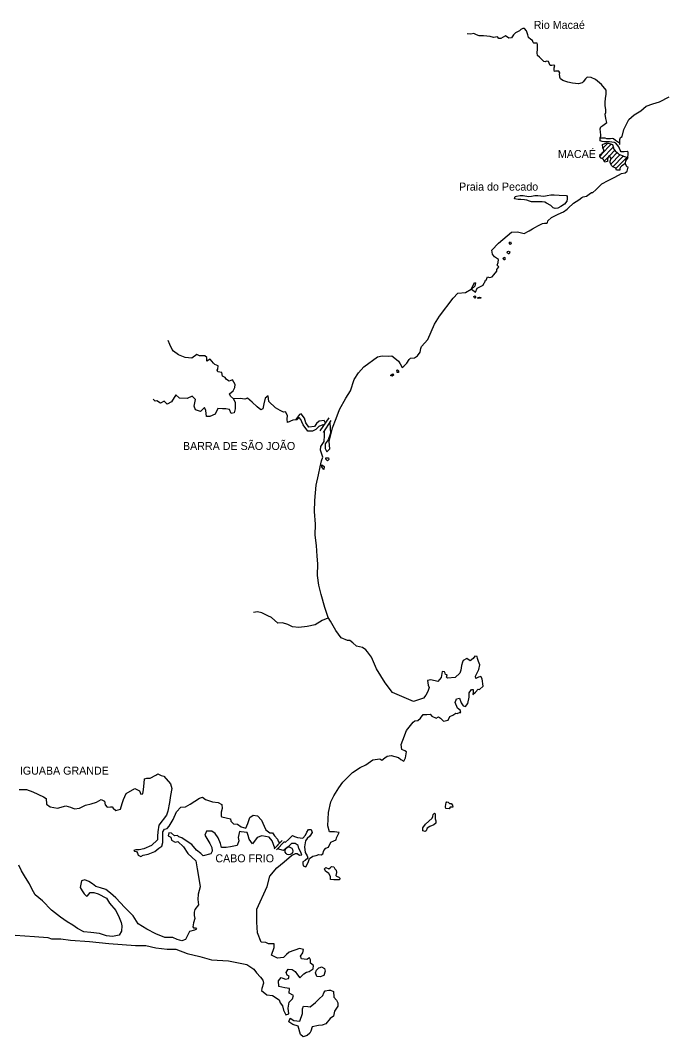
# Model space of a CAD drawing. Extents: x 662444 to 1640468, y 7452018 to 9606170.
# Drawn here: x 785069 to 836306, y 7452018 to 7532313 of the extents above; entities that cross this region are included whole.
import ezdxf

# ---------------------------------------------------------------- set-up
doc = ezdxf.new("R2010")
doc.units = 0
for name, color, linetype in [('Level 1', 7, 'Continuous'), ('Level 2', 7, 'Continuous'), ('Level 3', 7, 'Continuous')]:
    doc.layers.add(name, color=color, linetype=linetype)

msp = doc.modelspace()

# ---------------------------------------------------------------- linework, layer by layer
at = {"layer": 'Level 1'}
for points in [[(824206, 7531329), (824051, 7531162), (823878, 7530927), (823683, 7530899), (823398, 7531094), (823043, 7530879), (822878, 7530883), (822767, 7531007), (822466, 7530958), (822200, 7531030), (821665, 7531096), (821334, 7531092), (821109, 7531174), (820905, 7531267), (820667, 7531228), (820378, 7531234)], [(833086, 7521488), (833112, 7521743), (833115, 7521898), (833013, 7521956), (832785, 7521916), (832559, 7521921), (832469, 7522045), (832371, 7522324), (832141, 7522617), (832018, 7522664), (831822, 7522680), (831637, 7522717), (831421, 7522721), (831225, 7522726), (831050, 7522729), (830897, 7522799), (830891, 7523021), (830935, 7523164), (830938, 7523275), (830911, 7523486), (830896, 7523753), (830951, 7523907), (831108, 7524003), (831412, 7524241), (831347, 7524552), (831292, 7524897), (831336, 7525029), (831331, 7525251), (831296, 7525573), (831282, 7525851), (831309, 7526150), (831367, 7526481), (831353, 7526803), (831002, 7527254), (830515, 7527630), (830168, 7527804), (829859, 7527810), (829732, 7527691), (829552, 7527462), (829478, 7527386), (829188, 7527292), (828704, 7527358), (828334, 7527421), (827945, 7527552), (827752, 7527689), (827713, 7527823), (827704, 7527889), (827687, 7528034), (827710, 7528155), (827620, 7528290), (827362, 7528296), (827279, 7528264), (827262, 7528409), (827265, 7528564), (827300, 7528751), (827197, 7528776), (827062, 7528734), (826938, 7528737), (826850, 7528938), (826801, 7529050), (826770, 7529073), (826646, 7529076), (826552, 7529022), (826440, 7529069), (826289, 7529227), (826096, 7529409), (825934, 7529545), (825907, 7529734), (825934, 7530044), (825947, 7530155), (825952, 7530409), (825903, 7530521), (825645, 7530505), (825605, 7530561), (825546, 7530717), (825424, 7530786), (825231, 7530957), (825174, 7531180), (825077, 7531492), (824906, 7531662), (824777, 7531670), (824633, 7531580), (824519, 7531476), (824355, 7531411), (824206, 7531329)], [(830891, 7523021), (831066, 7523017), (831252, 7523024), (831395, 7522977), (831715, 7522981), (831850, 7523012), (831942, 7522987), (832104, 7522851), (832430, 7522633), (832427, 7522500), (832438, 7522544), (832446, 7522910), (832490, 7523064), (832636, 7523139), (832762, 7523691), (833170, 7524469), (833571, 7524859), (834103, 7525170), (834524, 7525526), (835043, 7525715), (835583, 7525880), (836355, 7526263)], [(823880, 7515576), (824359, 7515606), (824886, 7515465), (825292, 7515679), (825532, 7515829), (825793, 7515978), (825971, 7516086), (826325, 7516255), (826490, 7516296), (826532, 7516295), (826655, 7516282), (826686, 7516292), (826728, 7516325), (826762, 7516468), (827056, 7516728), (827577, 7517005), (828004, 7517184), (828276, 7517389), (828360, 7517476), (828781, 7517855), (829209, 7518134), (829450, 7518307), (829554, 7518360), (829803, 7518421), (830033, 7518582), (830211, 7518712), (830314, 7518710), (830546, 7518926), (830757, 7519144), (831020, 7519404), (831531, 7519659), (832000, 7519893), (832333, 7520074), (832584, 7520213), (832863, 7520262), (833021, 7520392), (833100, 7520723), (832987, 7520748), (832880, 7521038), (832764, 7520919), (832659, 7520843), (832565, 7520779), (832502, 7520703), (832438, 7520615), (832436, 7520527), (832435, 7520482), (832332, 7520485), (832188, 7520488), (832139, 7520622), (831883, 7520727), (831803, 7520817), (831684, 7521042), (831687, 7521197), (831764, 7521406), (831664, 7521563), (831624, 7521608), (831551, 7521555), (831464, 7521346), (831460, 7521157), (831252, 7521095), (831134, 7521353), (830960, 7521434), (830870, 7521558), (830895, 7521735), (831008, 7521732), (831041, 7521832), (831062, 7521864), (831166, 7521906), (831171, 7522117), (831112, 7522251), (831076, 7522507), (831253, 7522570), (831450, 7522632), (831870, 7522490), (831975, 7522122), (832086, 7522009), (832268, 7521839), (832379, 7521736), (832625, 7521631), (832747, 7521584), (833086, 7521488), (833011, 7521357), (832948, 7521303), (832884, 7521216), (832880, 7521038)], [(831767, 7522526), (831008, 7521744)], [(831928, 7522300), (831042, 7521399)], [(831491, 7522620), (831122, 7522240)], [(830998, 7521733), (830881, 7521602)], [(831540, 7521522), (831213, 7521185)], [(832046, 7522043), (831624, 7521608)], [(832461, 7521701), (831734, 7520952)], [(832238, 7521861), (831742, 7521351)], [(832727, 7521596), (831883, 7520727)], [(833014, 7521512), (832139, 7520611)], [(832436, 7520527), (832394, 7520483)], [(827536, 7517471), (827339, 7517453), (827186, 7517490), (826984, 7517683), (826657, 7517856), (826525, 7517936), (826299, 7517963), (825825, 7517973), (825701, 7517976), (825464, 7517981), (825311, 7518028), (825106, 7518110), (824911, 7518126), (824623, 7518154), (824406, 7518158), (824109, 7518220), (824164, 7518396), (824288, 7518427), (824578, 7518465), (824794, 7518461), (824928, 7518458), (825246, 7518407), (825473, 7518413), (825722, 7518485), (825969, 7518469), (826443, 7518426), (826712, 7518476), (827002, 7518536), (827269, 7518530), (827640, 7518511), (828227, 7518477), (828287, 7518387), (828283, 7518221), (828259, 7518022), (828068, 7517782), (827786, 7517610), (827536, 7517471)], [(809286, 7498216), (809518, 7498467), (809468, 7499044), (809747, 7500125), (810019, 7500862), (810301, 7501566), (810803, 7502453), (811155, 7503045), (811461, 7503937), (811801, 7504473), (812212, 7504930), (813289, 7505717), (813651, 7505799), (814145, 7505789), (814423, 7505794), (814657, 7505612), (814950, 7505373), (815080, 7505182), (815249, 7504890), (815375, 7504998), (815607, 7505238), (815787, 7505511), (815913, 7505619), (816213, 7505657), (816452, 7505797), (816654, 7506092), (816732, 7506378), (816766, 7506533), (817272, 7507088), (817791, 7508297), (818196, 7508942), (819266, 7510372), (819655, 7510752), (820254, 7510806), (820692, 7511074), (820863, 7511370), (820971, 7511590), (821043, 7511577), (820976, 7511312), (820734, 7511074), (821028, 7510846), (821179, 7511164), (821647, 7511398), (821713, 7511585), (821775, 7511617), (821841, 7511782), (821882, 7511792), (821990, 7512045), (822144, 7511998), (822361, 7512037), (822488, 7512212), (822731, 7512484), (822724, 7512628), (822873, 7512847), (822741, 7512972), (822828, 7513180), (822864, 7513413), (822549, 7513630), (822389, 7513844), (822343, 7514155), (822870, 7514698), (823880, 7515576)], [(823552, 7513984), (823569, 7514052), (823640, 7514084), (823742, 7514015), (823708, 7513860), (823636, 7513862), (823575, 7513919), (823552, 7513984)], [(823724, 7514647), (823727, 7514780), (823800, 7514801), (823859, 7514667), (823785, 7514602), (823724, 7514647)], [(823250, 7513444), (823236, 7513482), (823280, 7513614), (823351, 7513569), (823348, 7513402), (823266, 7513404), (823250, 7513444)], [(820987, 7510370), (820926, 7510415), (820917, 7510493), (820991, 7510547), (821031, 7510491), (821029, 7510402), (820987, 7510370)], [(821368, 7510362), (821316, 7510352), (821254, 7510331), (821204, 7510399), (821349, 7510440), (821451, 7510416), (821450, 7510360), (821368, 7510362)], [(809178, 7500491), (809079, 7500692), (808687, 7500656), (808477, 7500450), (808318, 7500231), (807874, 7500174), (807624, 7500522), (807518, 7500879), (807257, 7501217), (807132, 7501175), (806815, 7500760), (806609, 7500720), (806183, 7500551), (806147, 7500796), (806184, 7501105), (806035, 7501374), (805870, 7501366), (805595, 7501494), (805228, 7501690), (804713, 7502199), (804650, 7502643), (804409, 7502471), (804308, 7502018), (804238, 7501632), (804072, 7501546), (803799, 7501773), (803384, 7502136), (803009, 7502465), (802812, 7502391), (802453, 7502443), (801917, 7502409), (801674, 7502624), (801595, 7502792), (801899, 7503052), (802017, 7503305), (802052, 7503537), (801843, 7503907), (801563, 7503802), (801360, 7503939), (801260, 7504085), (801035, 7504189), (801000, 7504489), (800682, 7504550), (800623, 7504662), (800686, 7504761), (800712, 7505015), (800446, 7505120), (800345, 7505233), (800063, 7505538), (799813, 7505377), (799798, 7505676), (799656, 7505801), (799234, 7505809), (799030, 7505913), (798633, 7505610), (798089, 7505676), (797558, 7505897), (797172, 7506182), (797061, 7506317), (796873, 7506697), (796755, 7507010)], [(814446, 7504363), (814539, 7504395), (814567, 7504272), (814463, 7504197), (814340, 7504222), (814341, 7504288), (814446, 7504363)], [(814841, 7504577), (814813, 7504677), (814875, 7504698), (814966, 7504630), (814963, 7504497), (814860, 7504499), (814841, 7504577)], [(801917, 7502409), (802035, 7502119), (802045, 7501620), (801967, 7501311), (801719, 7501260), (801591, 7501562), (801304, 7501623), (801057, 7501628), (800676, 7501635), (800462, 7501196), (800057, 7501005), (799789, 7501010), (799737, 7501499), (799628, 7501722), (799303, 7501418), (798904, 7501537), (798807, 7501838), (798920, 7502357), (798647, 7502628), (798242, 7502448), (797656, 7502459), (797352, 7502720), (797012, 7502161), (796679, 7501990), (796436, 7502228), (796156, 7502078), (795850, 7502250), (795736, 7502219), (795575, 7502377)], [(809050, 7500305), (808980, 7500362), (808647, 7500225), (808416, 7499974), (808166, 7499846), (807796, 7499843), (807414, 7500349), (807327, 7500584), (807248, 7500785), (807097, 7500932), (806929, 7500758), (806815, 7500760)], [(808764, 7499879), (809464, 7500906)], [(809018, 7499740), (809635, 7500692)], [(809518, 7500506), (809594, 7499707), (809388, 7499179), (809155, 7498851), (809158, 7498485), (809286, 7498216)], [(808969, 7497790), (808785, 7498348), (808811, 7498636), (809087, 7499041), (809096, 7499506), (809103, 7499872)], [(821033, 7479239), (821244, 7479478), (821346, 7479454), (821650, 7479714), (821559, 7480281), (821471, 7480482), (821285, 7480431), (821066, 7480314), (821029, 7480492), (821297, 7481018), (821388, 7481404), (821270, 7481662), (821192, 7481885), (821165, 7482052), (820991, 7482089), (820843, 7481893), (820623, 7481698), (820359, 7481892), (820058, 7481732), (820003, 7481600), (819946, 7481335), (819877, 7480971), (819800, 7480728), (819433, 7480381), (818836, 7480349), (818755, 7480429), (818800, 7480605), (818677, 7480630), (818638, 7480742), (818599, 7480842), (818405, 7480868), (818323, 7480393), (818059, 7480089), (817506, 7480200), (817259, 7480161), (817302, 7479794), (817381, 7479604), (817282, 7479284), (817111, 7479011), (816921, 7478749), (816145, 7478510), (814484, 7479221), (813893, 7479965), (813227, 7481076), (812824, 7482004), (812504, 7482421), (812383, 7482567), (812120, 7482772), (811639, 7482860), (811346, 7483143), (811113, 7483314), (810918, 7483318), (810418, 7483528), (809998, 7484113), (809581, 7484853), (809392, 7485134), (809141, 7485937), (808842, 7486941), (808662, 7487676), (808564, 7488465), (808583, 7489363), (808523, 7489985), (808478, 7490828), (808381, 7491628), (808389, 7492515), (808306, 7493514), (808355, 7494389), (808451, 7495595), (808642, 7496400), (808758, 7497041), (808860, 7497504), (808969, 7497790)], [(808952, 7496948), (808892, 7497027), (808906, 7497204), (809088, 7497068), (809063, 7496835), (808952, 7496948)], [(809294, 7497573), (809233, 7497619), (809213, 7497652), (809215, 7497741), (809431, 7497748), (809449, 7497614), (809344, 7497517), (809294, 7497573)], [(809380, 7485090), (808914, 7484889), (808372, 7484545), (807742, 7484413), (807082, 7484349), (806579, 7484393), (806213, 7484588), (805784, 7484708), (805413, 7484693), (804928, 7485135), (804633, 7485263), (804144, 7485495), (803806, 7485579), (803496, 7485530)], [(805918, 7467402), (806020, 7467377), (806271, 7467605), (806575, 7467909), (806738, 7467839), (806962, 7467746), (807393, 7467704), (807593, 7467944), (807710, 7468163), (807838, 7468394), (808064, 7468389), (808141, 7468143), (807941, 7467870), (807731, 7467664), (807604, 7467489), (807533, 7467003), (807586, 7466581), (807734, 7466301), (807782, 7466122), (807573, 7465949), (807396, 7465831), (807393, 7465709), (807430, 7465509), (807634, 7465427), (807805, 7465767), (807915, 7466097), (808175, 7466269), (808443, 7466330), (808651, 7466415), (808835, 7466378), (808980, 7466475), (809058, 7466739), (809225, 7466902), (809412, 7466987), (809615, 7467382), (809833, 7467499), (810030, 7467562), (810064, 7467738), (810258, 7468145), (809899, 7468207), (809509, 7468193), (809375, 7468684), (809427, 7469736), (809599, 7470575), (809845, 7471046), (810227, 7471681), (810555, 7472129), (811331, 7472889), (811915, 7473276), (812382, 7473500), (812914, 7473877), (813470, 7473965), (813643, 7473850), (813883, 7474045), (814051, 7474186), (814370, 7474234), (814953, 7474078), (815134, 7473908), (815368, 7473781), (815497, 7474056), (815578, 7474509), (815447, 7474600), (815222, 7474693), (815159, 7475094), (815289, 7475446), (815583, 7476216), (816121, 7476870), (816246, 7476967), (816494, 7477006), (816692, 7477168), (816915, 7477463), (817192, 7477479), (817450, 7477485), (817591, 7477349), (817926, 7477176), (818124, 7477282), (818286, 7477168), (818507, 7476942), (818869, 7477034), (819009, 7477319), (819258, 7477425), (819487, 7477586), (819589, 7477540), (819786, 7477624), (819879, 7477634), (819831, 7477801), (819619, 7477972), (819433, 7478419), (819542, 7478716), (819769, 7478767), (819905, 7478398), (820054, 7478151), (820259, 7478091), (820428, 7478331), (820531, 7478839), (820539, 7479183), (820719, 7479456), (820853, 7479442), (820848, 7479243), (820834, 7479043), (821033, 7479239)], [(784971, 7471535), (785546, 7471535), (786046, 7471360), (786912, 7470966), (787104, 7470830), (787137, 7470386), (787421, 7470170), (787994, 7470081), (788665, 7470257), (789023, 7470139), (789359, 7470022), (789750, 7470070), (790228, 7470305), (790661, 7470418), (791095, 7470543), (791448, 7470747), (791723, 7470619), (791779, 7470330), (791920, 7470150), (792208, 7470189), (792321, 7470187), (792401, 7470074), (792613, 7469893), (792995, 7469985), (793117, 7470448), (793226, 7470768), (793430, 7471229), (794116, 7471626), (794482, 7471431), (794590, 7471174), (794745, 7471215), (794813, 7471535), (794854, 7472055), (794891, 7472398), (795067, 7472450), (795323, 7472434), (795770, 7472691), (795936, 7472788), (796211, 7472660), (796405, 7472601)], [(796405, 7472601), (796928, 7472004), (797054, 7471613), (796940, 7471072), (796868, 7470508), (796721, 7469846), (796612, 7469516), (796022, 7468740), (795929, 7468210), (795922, 7467856), (795906, 7467557), (795425, 7467112), (794824, 7466868), (794463, 7466787), (794196, 7466792), (794031, 7466729), (794091, 7466661), (794245, 7466658), (794324, 7466512), (794393, 7466356), (794586, 7466252), (794773, 7466348), (795175, 7466440), (795693, 7466641), (796027, 7466911), (796246, 7467073), (796334, 7467371), (796341, 7467759), (796330, 7468213), (796467, 7468410), (796684, 7468472), (796841, 7468647), (797139, 7469173), (797418, 7469777), (797765, 7470147), (798135, 7470184), (798488, 7470377), (799238, 7470861), (799475, 7470934), (799698, 7470763), (800259, 7470574), (800700, 7470521), (800984, 7470361), (801019, 7470049), (800952, 7469751), (800945, 7469408), (801006, 7469396), (801671, 7469216), (801698, 7469049), (801920, 7468823), (802237, 7468795), (802521, 7468601), (802878, 7468483), (803050, 7468856), (803204, 7469341), (803474, 7469524), (803802, 7469462), (804124, 7469112), (804330, 7468642), (804478, 7468362), (804782, 7468123), (805008, 7468118), (805147, 7467894), (805399, 7467634), (805436, 7467467), (805546, 7467309)], [(818968, 7470025), (818701, 7470042), (818663, 7470187), (818708, 7470374), (818711, 7470485), (818774, 7470584), (818876, 7470537), (818987, 7470435), (819110, 7470432), (819231, 7470308), (819238, 7470153), (819032, 7470146), (818968, 7470025)], [(817705, 7469575), (817789, 7469673), (817840, 7469628), (817852, 7469239), (817900, 7469061), (817896, 7468873), (817760, 7468743), (817418, 7468617), (817210, 7468499), (817144, 7468290), (817050, 7468236), (816876, 7468273), (816882, 7468517), (817083, 7468812), (817365, 7469050), (817627, 7469277), (817671, 7469410), (817705, 7469575)], [(805179, 7466918), (804974, 7467487), (804744, 7467769), (804151, 7467892), (803799, 7467766), (803429, 7467263), (803149, 7467613), (803072, 7467902), (802984, 7468137), (802524, 7468213), (802390, 7468215), (802278, 7467741), (802334, 7467485), (802204, 7467133), (801678, 7467010), (801338, 7466962), (800968, 7466969), (800882, 7467281), (800696, 7467717), (800466, 7468065), (800193, 7468259), (799771, 7468245), (799652, 7467937), (800040, 7467276), (800198, 7466951), (800233, 7466662), (800137, 7466476), (799528, 7466310), (799346, 7466480), (798982, 7466742), (798610, 7467193), (798083, 7467547), (797820, 7467730), (797595, 7467801), (797495, 7467902), (797258, 7467896), (797005, 7468089), (796800, 7468115), (796765, 7467894), (796958, 7467769), (797015, 7467546), (797299, 7467385), (797526, 7467425), (797960, 7467006), (798299, 7466490), (798934, 7465923), (799055, 7465267), (799184, 7464521), (799274, 7463866), (799129, 7463281), (799110, 7462849), (799143, 7462438), (798848, 7462067), (798813, 7461846), (798807, 7461580), (798854, 7461358), (798755, 7461005), (798697, 7460696), (798747, 7460628), (798922, 7460614), (798992, 7460524), (798846, 7460427), (798444, 7460324), (798327, 7460127), (798113, 7459699), (797844, 7459593), (797456, 7459701), (797110, 7459852), (796494, 7459842), (795781, 7460144), (795059, 7460513), (794380, 7460936), (793982, 7461576), (793337, 7462231), (792613, 7462977), (792189, 7463351), (791824, 7463635), (791396, 7463765), (791049, 7463871), (790766, 7464099), (790492, 7464281), (790176, 7464398), (789908, 7464337), (789795, 7463807), (789964, 7463538), (790113, 7463291), (790295, 7463110), (790388, 7463142), (790588, 7463404), (790885, 7463398), (791223, 7463314), (791873, 7462969), (792112, 7462565), (792624, 7461990), (792891, 7461442), (793037, 7461029), (793083, 7460784), (793075, 7460363), (792874, 7460045), (792358, 7459922), (791867, 7459976)], [(805749, 7467526), (805132, 7466868)], [(802960, 7457729), (803517, 7457352), (803727, 7457070), (804048, 7456720), (804238, 7456472), (804275, 7456239), (804143, 7455831), (804140, 7455665), (804554, 7455313), (804994, 7455260), (805521, 7454917), (805609, 7454704), (805778, 7454446), (805874, 7454111), (806061, 7453731), (806289, 7453815), (806236, 7454281), (806307, 7454734), (806590, 7455006), (806657, 7455282), (806322, 7455444), (806329, 7455820), (805971, 7455872), (805491, 7455970), (805469, 7456425), (805680, 7456698), (805812, 7456640), (806037, 7456569), (806274, 7456609), (806308, 7456785), (806145, 7456866), (806078, 7457100), (806237, 7457341), (806545, 7457335), (806778, 7457175), (806977, 7456893), (807168, 7456679), (807472, 7456972), (807680, 7457112), (807907, 7457174), (808219, 7457367), (808245, 7457644), (807992, 7457826), (807997, 7458081), (807919, 7458249), (807711, 7458120), (807291, 7458173), (807203, 7458385), (807393, 7458636), (807439, 7458902), (807143, 7458985), (806306, 7458703), (806097, 7458508), (805856, 7458269), (805403, 7458211), (804925, 7458454), (805133, 7459059), (805118, 7459359), (804687, 7459346), (804463, 7459450), (804094, 7459491), (803801, 7460228), (803756, 7461060), (803766, 7462080), (804573, 7463882), (804785, 7464709), (805342, 7465351), (805907, 7465839), (806492, 7466326), (806814, 7466497), (806957, 7466494), (807140, 7466368), (807304, 7466387), (807207, 7466644), (807088, 7466879), (807021, 7467124), (806799, 7467284), (806490, 7467268), (806228, 7467007), (805863, 7466715), (805393, 7466858)], [(805546, 7467309), (805179, 7466918)], [(805546, 7467309), (805179, 7466918)], [(805949, 7467434), (805320, 7466782)], [(791867, 7459976), (791337, 7460175), (790650, 7460244), (790076, 7460310), (789579, 7460575), (789214, 7460837), (788767, 7461100), (788240, 7461454), (787543, 7462021), (786817, 7462744), (786241, 7463221), (785973, 7463691), (785785, 7464094), (785477, 7464599), (785168, 7465125), (784941, 7465573)], [(809585, 7465387), (809668, 7465452), (809833, 7465448), (809932, 7465291), (810042, 7465167), (810049, 7464989), (810003, 7464758), (810053, 7464690), (810237, 7464631), (810317, 7464529), (810304, 7464419), (810068, 7464413), (809842, 7464406), (809585, 7464423), (809570, 7464678), (809441, 7464913), (809178, 7465085), (809120, 7465286), (809225, 7465394), (809449, 7465290), (809585, 7465387)], [(784662, 7460048), (786199, 7459919), (787245, 7459844), (787541, 7459760), (788280, 7459757), (789037, 7459643), (790534, 7459525), (792071, 7459385), (794161, 7459211), (794459, 7459216), (794983, 7459217), (795769, 7459025), (796661, 7458940), (797369, 7458927), (798255, 7458588), (799256, 7458346), (800175, 7458084), (801518, 7458002), (802040, 7457902), (802960, 7457729)], [(808776, 7457489), (808879, 7457531), (809103, 7457404), (809170, 7457203), (809061, 7456862), (808761, 7456757), (808494, 7456774), (808397, 7457053), (808474, 7457273), (808672, 7457446), (808776, 7457489)], [(809053, 7455487), (809148, 7455630), (809447, 7455701), (809581, 7455698), (809815, 7455594), (809836, 7455139), (810057, 7454890), (810155, 7454689), (810160, 7454434), (809885, 7454040), (809815, 7453632), (809545, 7453460), (809218, 7453023), (808928, 7452918), (808630, 7452902), (808136, 7452801), (808036, 7452460), (807940, 7452284), (807742, 7452122), (807422, 7452018), (807199, 7452189), (807018, 7452858), (806610, 7452977), (806296, 7453194), (806384, 7453480), (806678, 7453286), (807149, 7453232), (807357, 7453848), (807364, 7454214), (807440, 7454423), (807789, 7454405), (807973, 7454368), (808401, 7454714), (808694, 7455018), (808966, 7455279), (809053, 7455487)]]:
    msp.add_lwpolyline(points, dxfattribs=at)
at = {"layer": 'Level 2'}
msp.add_ellipse((806294, 7466696), major_axis=(13, 308), ratio=0.999991, dxfattribs=at)

# ---------------------------------------------------------------- texts
at = {"layer": 'Level 3'}
for s, height, p in [('Rio Macaé', 633.1, (825638, 7531635)), ('MACAÉ', 632.7, (827548, 7521436)), ('Praia do Pecado', 632.59, (819740, 7518858)), ('BARRA DE SÃO JOÃO', 631.63, (797922, 7498370)), ('IGUABA GRANDE', 630.5, (785034, 7472720)), ('CABO FRIO', 630.3, (800483, 7465793))]:
    msp.add_text(s, height=height, dxfattribs=at).set_placement(p)

doc.saveas('drawing.dxf')
